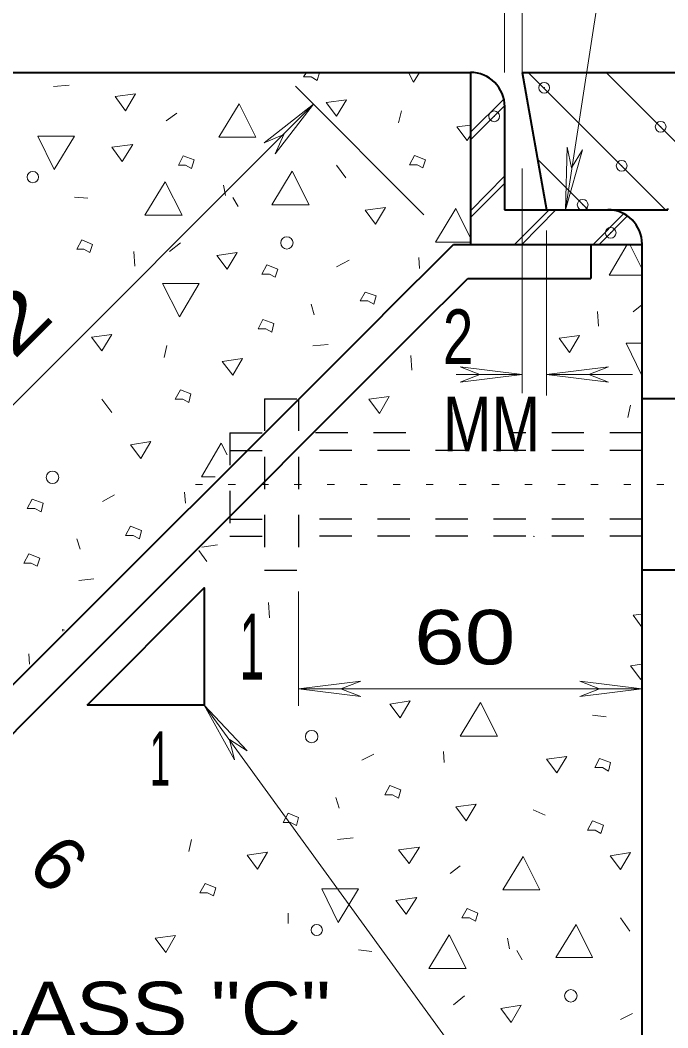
# Model space of a CAD drawing. Extents: x 312583 to 312854, y 144419 to 144597.
# Drawn here: x 312640.43 to 312649.47, y 144462.01 to 144476.07 of the extents above; entities that cross this region are included whole.
import ezdxf
from ezdxf.enums import TextEntityAlignment as Align

# ---------------------------------------------------------------- set-up
doc = ezdxf.new("R2010")
doc.units = 0
doc.header["$LTSCALE"] = 0.3
doc.header["$PDMODE"] = 32
doc.header["$PDSIZE"] = 0.15
doc.linetypes.add('DOTTED', pattern=[1.5, 0.3, -1.2])
doc.linetypes.add('SHORT_DASHED', pattern=[2.7, 1.5, -1.2])
doc.layers.add('1', color=7, linetype='Continuous', lineweight=13)

msp = doc.modelspace()

# ---------------------------------------------------------------- linework, layer by layer
at = {"layer": '1'}
for p, q in [((312647.438, 144475.3431), (312647.438, 144483.7611)), ((312647.1927, 144475.3431), (312647.1927, 144479.7361)), ((312648.7414, 144477.9727), (312648.0437, 144473.4264)), ((312647.5224, 144475.3431), (312649.439, 144473.4264)), ((312648.611, 144475.3431), (312650.0447, 144473.9017)), ((312641.113, 144475.1667), (312640.8984, 144475.1437)), ((312646.0657, 144473.3574), (312644.2717, 144475.1514)), ((312646.7174, 144474.5074), (312647.185, 144474.9751)), ((312636.3904, 144466.7641), (312644.5247, 144474.8984)), ((312644.5247, 144474.8984), (312643.8347, 144474.3617)), ((312644.5247, 144474.8984), (312643.988, 144474.2084)), ((312645.7514, 144474.8064), (312645.713, 144474.6377)), ((312646.7174, 144474.4001), (312647.1927, 144474.8754)), ((312642.6157, 144474.7757), (312642.47, 144474.6684)), ((312646.7174, 144474.6071), (312646.5257, 144474.5841)), ((312643.8347, 144474.3617), (312644.1107, 144474.4767)), ((312643.988, 144474.2084), (312644.1107, 144474.4767)), ((312648.0437, 144473.4264), (312648.0667, 144474.3004)), ((312648.0437, 144473.4264), (312648.2814, 144474.2621)), ((312648.0667, 144474.3004), (312648.128, 144474.0091)), ((312648.2814, 144474.2621), (312648.128, 144474.0091)), ((312647.6527, 144474.1317), (312648.358, 144473.4264)), ((312644.977, 144473.8711), (312644.8467, 144474.0474)), ((312647.438, 144474.0014), (312647.438, 144470.8657)), ((312646.7174, 144473.4111), (312647.1927, 144473.8941)), ((312646.7174, 144473.3191), (312647.1927, 144473.7944)), ((312643.2674, 144473.7714), (312643.298, 144473.6257)), ((312641.1897, 144473.6027), (312641.3737, 144473.5874)), ((312643.3977, 144473.5951), (312643.4744, 144473.4724)), ((312647.3307, 144472.9434), (312647.8137, 144473.4264)), ((312647.4304, 144472.9434), (312647.9057, 144473.4264)), ((312648.427, 144472.9434), (312648.8564, 144473.3727)), ((312648.5114, 144472.9434), (312648.9024, 144473.3344)), ((312647.7754, 144473.1351), (312647.7754, 144470.8351)), ((312642.6694, 144472.9664), (312642.516, 144472.8437)), ((312646.2267, 144472.9741), (312646.7174, 144472.9741)), ((312642.0177, 144472.8437), (312642.033, 144472.6367)), ((312648.9024, 144472.9434), (312648.6494, 144472.5141)), ((312649.1094, 144472.6061), (312648.9407, 144472.9434)), ((312645.023, 144472.7211), (312644.8467, 144472.6291)), ((312645.9967, 144472.7594), (312646.0044, 144472.6061)), ((312648.6494, 144472.5141), (312649.1094, 144472.5141)), ((312644.494, 144472.1077), (312644.5324, 144471.9621)), ((312648.4884, 144472.0081), (312648.5037, 144471.8011)), ((312649.1094, 144472.1001), (312648.9867, 144472.0004)), ((312644.7317, 144471.5481), (312644.517, 144471.5251)), ((312642.4777, 144471.5327), (312642.4394, 144471.3641)), ((312645.8817, 144471.3947), (312645.897, 144471.1877)), ((312646.518, 144471.1264), (312647.438, 144471.1264)), ((312646.5717, 144471.2337), (312646.8477, 144471.1264)), ((312647.438, 144471.1264), (312646.5717, 144471.2337)), ((312646.5717, 144471.0191), (312646.8477, 144471.1264)), ((312647.438, 144471.1264), (312646.5717, 144471.0191)), ((312647.7754, 144471.1264), (312648.6417, 144471.2337)), ((312647.7754, 144471.1264), (312648.979, 144471.1264)), ((312647.7754, 144471.1264), (312648.6417, 144471.0191)), ((312648.6417, 144471.2337), (312648.3657, 144471.1264)), ((312648.6417, 144471.0191), (312648.3657, 144471.1264)), ((312641.711, 144470.5974), (312641.573, 144470.7814)), ((312648.9484, 144470.6971), (312648.91, 144470.5284)), ((312642.9607, 144469.7004), (312643.1524, 144469.7004)), ((312641.7494, 144469.4474), (312641.5807, 144469.3554)), ((312642.723, 144469.4857), (312642.7384, 144469.3324)), ((312641.2204, 144468.8341), (312641.2664, 144468.6884)), ((312643.183, 144468.7497), (312642.9684, 144468.7191)), ((312642.9224, 144468.6731), (312643.0374, 144468.5197)), ((312641.458, 144468.2744), (312641.251, 144468.2514)), ((312644.3177, 144466.5034), (312644.3177, 144468.0981)), ((312643.896, 144467.9447), (312643.9114, 144467.7301)), ((312649.1094, 144467.7837), (312648.9867, 144467.7684)), ((312648.9867, 144467.7684), (312649.1094, 144467.5997)), ((312640.5534, 144467.2317), (312640.561, 144467.0861)), ((312649.1094, 144467.0861), (312648.9484, 144467.0631)), ((312644.3177, 144466.7411), (312645.184, 144466.8484)), ((312645.184, 144466.8484), (312644.908, 144466.7411)), ((312648.243, 144466.8484), (312648.519, 144466.7411)), ((312649.1094, 144466.7411), (312648.243, 144466.8484)), ((312644.3177, 144466.7411), (312649.1094, 144466.7411)), ((312644.3177, 144466.7411), (312645.184, 144466.6337)), ((312645.184, 144466.6337), (312644.908, 144466.7411)), ((312648.243, 144466.6337), (312648.519, 144466.7411)), ((312649.1094, 144466.7411), (312648.243, 144466.6337)), ((312642.999, 144466.5111), (312643.4207, 144465.7521)), ((312642.999, 144466.5111), (312643.597, 144465.8747)), ((312648.4194, 144466.3731), (312648.611, 144466.3501)), ((312643.4207, 144465.7521), (312643.3517, 144466.0357)), ((312643.597, 144465.8747), (312643.3517, 144466.0357)), ((312645.368, 144465.8287), (312645.1994, 144465.7444)), ((312646.3417, 144465.8671), (312646.3494, 144465.7137)), ((312644.839, 144465.2231), (312644.885, 144465.0774)), ((312647.76, 144464.9777), (312647.5914, 144465.0544)), ((312645.0767, 144464.6634), (312644.862, 144464.6404)), ((312642.8227, 144464.6404), (312642.7844, 144464.4717)), ((312646.5717, 144464.2724), (312646.4337, 144464.1651)), ((312644.172, 144463.6131), (312644.172, 144463.4674)), ((312648.9407, 144463.3601), (312648.8104, 144463.5441)), ((312647.231, 144463.2604), (312647.2617, 144463.1147)), ((312645.1534, 144463.0994), (312645.3374, 144463.0764)), ((312647.3614, 144463.0917), (312647.438, 144462.9614)), ((312646.633, 144462.4554), (312646.4797, 144462.3327)), ((312648.979, 144462.2101), (312648.8104, 144462.1257))]:
    msp.add_line(p, q, dxfattribs=at)
at = {"layer": '1', "lineweight": 40}
for p, q in [((312633.776, 144475.3431), (312646.7174, 144475.3431)), ((312646.7174, 144475.3431), (312646.7174, 144472.9434)), ((312647.438, 144475.3431), (312647.7754, 144473.4264)), ((312647.438, 144475.3431), (312665.5544, 144475.3431)), ((312647.1927, 144474.8601), (312647.1927, 144473.4264)), ((312647.1927, 144473.4264), (312649.4697, 144473.4264)), ((312649.4697, 144473.4264), (312649.4697, 144473.4417)), ((312645.4907, 144471.9621), (312646.4797, 144472.9434)), ((312646.4797, 144472.9434), (312649.1094, 144472.9434)), ((312648.3964, 144472.9434), (312648.3964, 144472.4681)), ((312649.1094, 144472.9434), (312649.1094, 144458.3767)), ((312646.679, 144472.4681), (312648.3964, 144472.4681)), ((312638.3454, 144464.8167), (312645.4907, 144471.9544)), ((312649.1094, 144471.0267), (312649.1094, 144468.1517)), ((312649.5924, 144470.7891), (312649.1094, 144470.7891)), ((312649.5924, 144468.3971), (312649.1094, 144468.3971))]:
    msp.add_line(p, q, dxfattribs=at)
at = {"layer": '1', "linetype": 'SHORT_DASHED', "lineweight": 25}
for p, q in [((312643.8424, 144470.7891), (312643.8424, 144468.3971)), ((312643.8424, 144470.7891), (312644.3177, 144470.7891)), ((312644.3177, 144470.7891), (312644.3177, 144468.3971)), ((312643.3594, 144470.3137), (312643.3594, 144468.8724)), ((312643.3594, 144470.3137), (312643.8424, 144470.3137)), ((312645.8127, 144470.3137), (312644.3177, 144470.3137)), ((312649.1094, 144470.3137), (312647.2464, 144470.3137)), ((312643.3594, 144470.0684), (312643.8424, 144470.0684)), ((312649.1094, 144470.0684), (312644.3177, 144470.0684)), ((312643.3594, 144469.1101), (312643.8424, 144469.1101)), ((312649.1094, 144469.1101), (312644.3177, 144469.1101)), ((312643.3594, 144468.8724), (312643.8424, 144468.8724)), ((312649.1094, 144468.8724), (312644.3177, 144468.8724)), ((312643.8424, 144468.3971), (312644.3177, 144468.3971))]:
    msp.add_line(p, q, dxfattribs=at)
at = {"layer": '1', "linetype": 'DOTTED'}
msp.add_line((312650.796, 144469.5931), (312642.5697, 144469.5931), dxfattribs=at)
at = {"layer": '1'}
for points in [[(312644.425, 144475.3431), (312644.3867, 144475.2817), (312644.494, 144475.2817)], [(312644.494, 144475.2817), (312644.5784, 144475.2281), (312644.609, 144475.3431)], [(312645.851, 144475.3431), (312645.92, 144475.2051), (312646.0044, 144475.3431)], [(312646.5257, 144474.5841), (312646.6714, 144474.3924), (312646.7174, 144474.4691)], [(312646.7174, 144473.0277), (312646.5104, 144473.4417), (312646.2267, 144472.9741)], [(312649.1094, 144471.5634), (312648.887, 144471.5634), (312649.1094, 144471.1111)], [(312643.321, 144470.0071), (312643.2367, 144470.1681), (312642.9607, 144469.7004)], [(312647.5914, 144468.8724), (312647.6067, 144468.8647), (312647.6067, 144468.8724)], [(312641.0517, 144467.5614), (312641.021, 144467.5691), (312641.0287, 144467.5461)], [(312648.9484, 144467.0631), (312649.094, 144466.8714), (312649.1094, 144466.9021)], [(312652.6207, 144454.8961), (312651.44, 144454.8961), (312642.999, 144466.5111)]]:
    msp.add_lwpolyline(points, dxfattribs=at)
for points in [[(312641.757, 144475.0057), (312641.9027, 144474.8064), (312642.0407, 144475.0441)], [(312644.701, 144474.9214), (312644.8467, 144474.7297), (312644.9847, 144474.9597)], [(312643.206, 144474.4384), (312643.7197, 144474.4384), (312643.4897, 144474.9061)], [(312641.1897, 144474.4537), (312640.676, 144474.4537), (312640.906, 144473.9861)], [(312641.711, 144474.3004), (312641.8567, 144474.1011), (312642.0024, 144474.3387)], [(312642.7384, 144474.0474), (312642.8227, 144474.0014), (312642.861, 144474.1241), (312642.7077, 144474.1777), (312642.6387, 144474.0474)], [(312645.9737, 144474.0551), (312646.0504, 144474.0091), (312646.0887, 144474.1241), (312645.9354, 144474.1854), (312645.8664, 144474.0551)], [(312643.942, 144473.4954), (312644.4634, 144473.4954), (312644.2257, 144473.9631)], [(312642.171, 144473.3497), (312642.6924, 144473.3497), (312642.4547, 144473.8174)], [(312645.2454, 144473.4187), (312645.391, 144473.2271), (312645.529, 144473.4571)], [(312641.32, 144472.8744), (312641.4044, 144472.8284), (312641.4427, 144472.9434), (312641.2894, 144473.0047), (312641.2204, 144472.8744)], [(312643.1754, 144472.7901), (312643.321, 144472.5984), (312643.459, 144472.8284)], [(312643.9114, 144472.5294), (312643.988, 144472.4834), (312644.0264, 144472.5984), (312643.873, 144472.6597), (312643.804, 144472.5294)], [(312642.93, 144472.3991), (312642.4164, 144472.3991), (312642.654, 144471.9314)], [(312645.2837, 144472.1537), (312645.368, 144472.1077), (312645.3987, 144472.2227), (312645.2454, 144472.2764), (312645.1764, 144472.1537)], [(312643.8577, 144471.7627), (312643.942, 144471.7167), (312643.9727, 144471.8394), (312643.8194, 144471.8931), (312643.7504, 144471.7627)], [(312641.4274, 144471.6477), (312641.573, 144471.4561), (312641.711, 144471.6861)], [(312647.9517, 144471.6324), (312648.0974, 144471.4331), (312648.2354, 144471.6707)], [(312643.252, 144471.3104), (312643.3977, 144471.1187), (312643.5357, 144471.3487)], [(312642.7, 144470.7814), (312642.7844, 144470.7354), (312642.815, 144470.8581), (312642.6694, 144470.9117), (312642.5927, 144470.7814)], [(312645.299, 144470.7814), (312645.4447, 144470.5821), (312645.5827, 144470.8197)], [(312641.9717, 144470.1451), (312642.1174, 144469.9534), (312642.2554, 144470.1911)], [(312640.6377, 144469.2557), (312640.722, 144469.2097), (312640.7527, 144469.3324), (312640.5994, 144469.3861), (312640.5304, 144469.2557)], [(312642.01, 144468.8801), (312642.0944, 144468.8341), (312642.125, 144468.9491), (312641.9717, 144469.0104), (312641.9027, 144468.8801)], [(312640.584, 144468.4967), (312640.6684, 144468.4507), (312640.7067, 144468.5657), (312640.5534, 144468.6271), (312640.4844, 144468.4967)], [(312645.5904, 144466.5264), (312645.736, 144466.3347), (312645.874, 144466.5724)], [(312646.5717, 144466.0817), (312647.093, 144466.0817), (312646.8554, 144466.5494)], [(312647.7754, 144465.7597), (312647.921, 144465.5681), (312648.059, 144465.7981)], [(312648.5574, 144465.6447), (312648.6417, 144465.5911), (312648.6724, 144465.7137), (312648.519, 144465.7674), (312648.45, 144465.6447)], [(312645.6287, 144465.2614), (312645.713, 144465.2154), (312645.7437, 144465.3304), (312645.5904, 144465.3917), (312645.5214, 144465.2614)], [(312646.5104, 144465.0927), (312646.656, 144464.9011), (312646.794, 144465.1311)], [(312644.2027, 144464.8781), (312644.287, 144464.8321), (312644.3177, 144464.9471), (312644.172, 144465.0084), (312644.103, 144464.8781)], [(312648.4577, 144464.7707), (312648.5344, 144464.7247), (312648.5727, 144464.8397), (312648.4194, 144464.9011), (312648.3504, 144464.7707)], [(312645.713, 144464.4947), (312645.8587, 144464.3031), (312646.0044, 144464.5331)], [(312643.597, 144464.4181), (312643.7427, 144464.2264), (312643.8807, 144464.4641)], [(312647.1697, 144463.9351), (312647.6834, 144463.9351), (312647.4534, 144464.4027)], [(312648.6647, 144464.4104), (312648.8104, 144464.2187), (312648.9484, 144464.4564)], [(312643.045, 144463.8967), (312643.1294, 144463.8507), (312643.16, 144463.9657), (312643.0144, 144464.0271), (312642.9377, 144463.8967)], [(312645.1534, 144463.9504), (312644.6397, 144463.9504), (312644.8697, 144463.4827)], [(312645.6747, 144463.7894), (312645.8204, 144463.5977), (312645.966, 144463.8277)], [(312646.702, 144463.5441), (312646.7864, 144463.4981), (312646.817, 144463.6131), (312646.6714, 144463.6744), (312646.5947, 144463.5441)], [(312647.9057, 144462.9921), (312648.4194, 144462.9921), (312648.1894, 144463.4521)], [(312642.3167, 144463.2604), (312642.4624, 144463.0611), (312642.6004, 144463.2987)], [(312646.1347, 144462.8387), (312646.656, 144462.8387), (312646.4184, 144463.3064)], [(312647.139, 144462.2791), (312647.2847, 144462.0874), (312647.4227, 144462.3251)]]:
    msp.add_lwpolyline(points, close=True, dxfattribs=at)
at = {"layer": '1', "lineweight": 40}
msp.add_lwpolyline([(312638.514, 144464.3031), (312645.9507, 144471.7397), (312646.679, 144472.4681)], dxfattribs=at)
msp.add_lwpolyline([(312641.366, 144466.5111), (312642.999, 144468.1517), (312642.999, 144466.5111)], close=True, dxfattribs=at)
at = {"layer": '1'}
for centre, radius in [((312640.6077, 144473.8821), 0.0784), ((312644.1539, 144472.9637), 0.0865), ((312640.8822, 144469.6921), 0.0865), ((312644.4995, 144466.0748), 0.0865), ((312644.5705, 144463.3759), 0.0784), ((312648.1168, 144462.4575), 0.0865)]:
    msp.add_circle(centre, radius, dxfattribs=at)
at = {"layer": '1', "lineweight": 40}
for centre in [(312646.7155, 144474.8639), (312648.6321, 144472.9472)]:
    msp.add_arc(centre, 0.4792, 0, 90, dxfattribs=at)
at = {"layer": '1'}
for p in [(312647.7447, 144475.1284), (312647.047, 144474.7297), (312649.37, 144474.5841), (312648.8257, 144474.0397), (312648.2814, 144473.4954), (312648.6724, 144473.1044)]:
    msp.add_point(p, dxfattribs=at)

# ---------------------------------------------------------------- texts
at = {"layer": '1', "width": 1.5}
msp.add_text('152 ', height=0.76, rotation=45, dxfattribs=at).set_placement((312639.1368, 144470.1147))
at = {"layer": '1'}
for s, width, p in [('2', 0.75, (312646.3314, 144471.2759)), ('MM', 0.8, (312646.3314, 144470.0559)), ('60 ', 1.25, (312645.9295, 144467.0823)), ('1', 0.5, (312642.2409, 144465.3879)), ('CLASS "C"', 1.15, (312638.9357, 144461.8947))]:
    msp.add_text(s, height=0.76, dxfattribs=dict(at, width=width)).set_placement(p)
at = {"layer": '1', "width": 0.5}
msp.add_text('1', height=0.92, dxfattribs=at).set_placement((312643.666, 144466.8714), align=Align.CENTER)
at = {"layer": '1'}
msp.add_text('6', height=0.76, rotation=315, dxfattribs=at).set_placement((312640.5025, 144464.2392))

doc.saveas('drawing.dxf')
